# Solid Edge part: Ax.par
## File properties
Author: Ionut
Template: Normal.par
Last saved by: Ionut
Revision: 8
Application: Solid Edge
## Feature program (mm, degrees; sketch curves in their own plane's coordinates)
sketch for "unnamed Protrusion 1" plane through (0, 0, 0) normal (1, 0, 0) x-axis (0, 1, 0)
  circle centre (0, 0) radius 4
extrude "unnamed Protrusion 1" add finite 46 along +normal
sketch for "unnamed Protrusion 2" plane through (46, 0, 0) normal (1, 0, 0) x-axis (0, 1, 0)
  line (0, 0) -> (0, 0)
  circle centre (0, 0) radius 7
extrude "unnamed Protrusion 2" add finite 2 along +normal
sketch for "unnamed Cutout 1" plane through (48, 0, 0) normal (1, 0, 0) x-axis (0, 1, 0)
  circle centre (0, 7) radius 1
extrude "unnamed Cutout 1" cut through along -normal
sketch used by "unnamed Cutout 2" plane through (0, 0, 0) normal (-1, 0, 0) x-axis (0, 0, 1)
extrude "unnamed Cutout 2" cut finite 40 along -normal
pattern "unnamed Pattern 1" of "unnamed Cutout 2"
extrude "unnamed Cutout 3" cut finite 40
extrude "unnamed Cutout 4" cut finite 40
extrude "unnamed Cutout 5" cut finite 40
extrude "unnamed Cutout 6" cut finite 40
extrude "unnamed Cutout 7" cut finite 40
extrude "unnamed Cutout 8" cut finite 40
extrude "unnamed Cutout 9" cut finite 40
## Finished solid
Body 1: solid body, 22 faces, 55 edges, 36 vertices.
  Faces by surface: cylinder 11, plane 11
  Edges by curve: circle 37, line 18
Bounding box of the edges (mm): 48.000 x 14.000 x 13.929, from (0, -7, -7) to (48, 7, 6.9286).
Cylindrical faces by radius (mm): R1 x9, R4 x1, R7 x1
Planar faces by outward normal: +x 1, -x 10
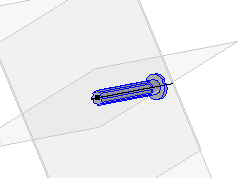
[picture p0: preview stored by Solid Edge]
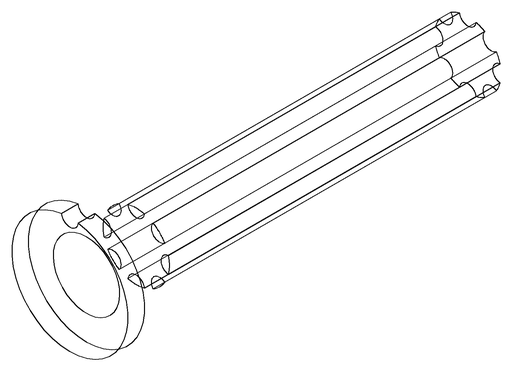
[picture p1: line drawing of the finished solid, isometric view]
